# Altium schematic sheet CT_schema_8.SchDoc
size 226 x 144 mm
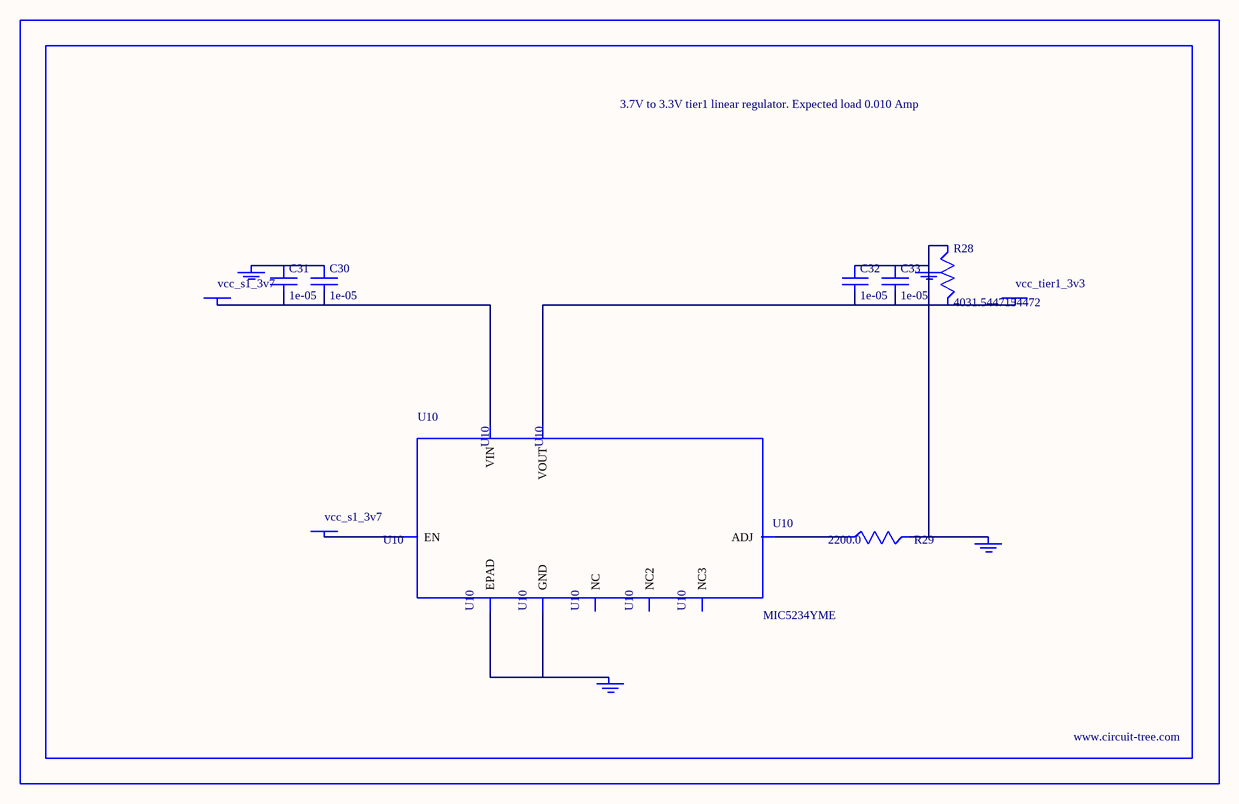
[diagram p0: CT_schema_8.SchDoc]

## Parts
BORDER7  (no value)
C30  1e-05  [C1210]
C31  1e-05  [C1210]
C32  1e-05  [C1210]
C33  1e-05  [C1210]
GND_INSTANCE_7_0  (no value)
GND_INSTANCE_7_1  (no value)
GND_INSTANCE_7_2  (no value)
GND_INSTANCE_7_3  (no value)
POWER_INSTANCE_7_0  vcc_tier1_3v3
POWER_INSTANCE_7_1  vcc_s1_3v7
POWER_INSTANCE_7_2  vcc_s1_3v7
R28  4031.5447154472  [R0603]
R29  2200.0  [R0603]
U10  MIC5234YME  [SOIC-8_EP]

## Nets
NetC30_1: C30.1 C31.1 GND_INSTANCE_7_3.0(GND)
NetC30_2: C30.2 C31.2 POWER_INSTANCE_7_2.0(PWR) U10.8(VIN)
NetC32_1: C32.1 C33.1 GND_INSTANCE_7_0.0(GND) GND_INSTANCE_7_1.0(GND) R28.1 R29.2
NetC32_2: C32.2 C33.2 POWER_INSTANCE_7_0.0(PWR) R28.2 U10.1(VOUT)
NetGND_INSTANCE_7_2_0: GND_INSTANCE_7_2.0(GND) U10.7(GND) U10.EPAD
NetPOWER_INSTANCE_7_1_0: POWER_INSTANCE_7_1.0(PWR) U10.5(EN)
NetR29_1: R29.1 U10.4(ADJ)

Not connected (* = marked no-connect by the designer): U10 2(NC) 3(NC2) 6(NC3)

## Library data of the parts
BORDER7 = BORDER_PAGE7
C30-C33 = C1210C106K5PACTU
GND_INSTANCE_7_0-GND_INSTANCE_7_3 = GND
POWER_INSTANCE_7_0-POWER_INSTANCE_7_2 = PWR
R28 = R28
R29 = RC0603JR-072K2L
